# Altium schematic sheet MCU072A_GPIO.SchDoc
size 431 x 279 mm; Date: Not shown in title block; ApprovedBy: Not shown in title block; CheckedBy: Not shown in title block; Author: Not shown in title block; CompanyName: Not shown in title block; DrawnBy: Cody Watkins; Engineer: Not shown in title block; Organization: Not shown in title block; Address1: Not shown in title block; Address2: Not shown in title block; Address3: Not shown in title block; Address4: Not shown in title block; DocumentNumber: 2; Revision: Use project parameter SCH_Rev; SheetNumber: 2; SheetTotal: 7; PageSetup: Record=PageOptions¦CenterHorizontal=True¦CenterVertical=True¦PrintScale=1.00¦XCorrection=1.00¦YCorrection=1.00¦PrintKind=0¦BorderSize=5000000¦LeftOffset=0¦BottomOffset=0¦Orientation=2¦PaperLength=1000¦PaperWidth=1000¦Scale=100¦PaperSource=15¦PrintQuality=600¦MediaType=1¦DitherType=10¦PaperKind=Letter¦PrintScaleMode=1
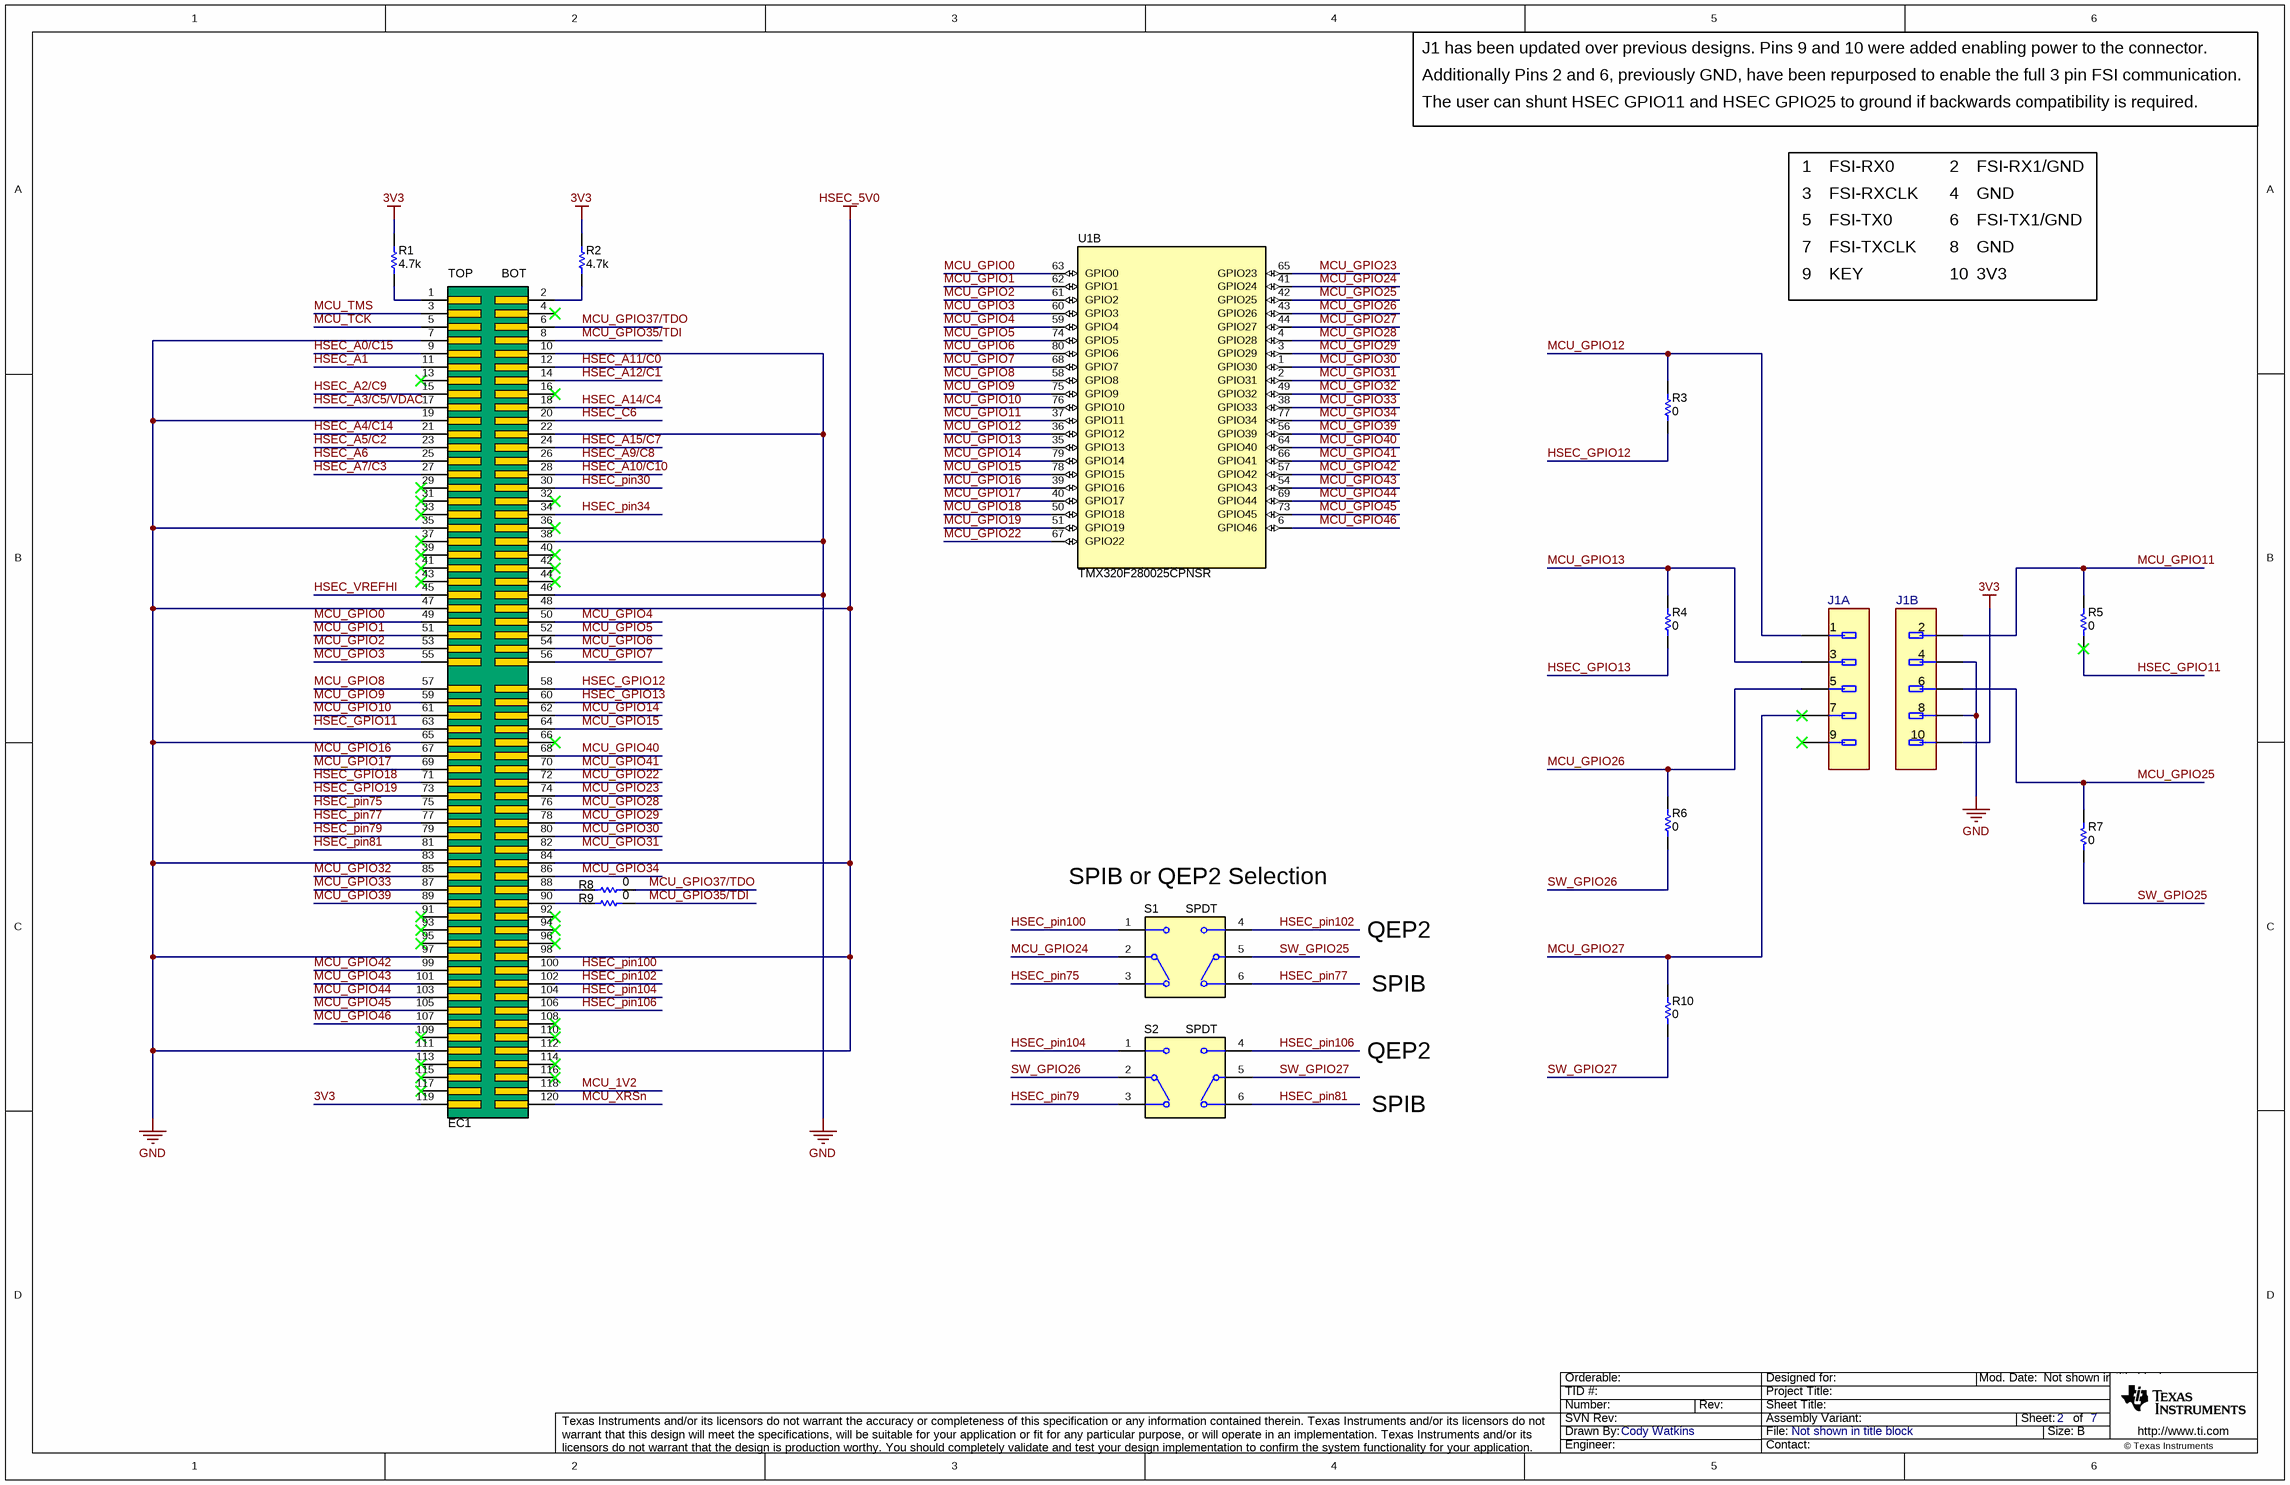
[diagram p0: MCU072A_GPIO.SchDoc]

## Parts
EC1  controlCARD-120HSEC_Edge  [controlCARD-120HSEC_Edge]  (value not drawn)  (no BOM)
J1  TMM-105-01-T-D  [FP-TMM-105-01-T-D_HDR10-MFG]  (value not drawn)  (parts A,B of 2)
R1  ValueDisplayed: 4.7k  [0402]  (hidden comment: CRCW04024K70JNED)
R2  ValueDisplayed: 4.7k  [0402]  (hidden comment: CRCW04024K70JNED)
R3  ValueDisplayed: 0  [0603]  (hidden comment: CRCW06030000Z0EA)
R4  ValueDisplayed: 0  [0603]  (hidden comment: CRCW06030000Z0EA)
R5  ValueDisplayed: 0  [0603]  (hidden comment: CRCW06030000Z0EA)
R6  ValueDisplayed: 0  [0603]  (hidden comment: CRCW06030000Z0EA)
R7  ValueDisplayed: 0  [0603]  (hidden comment: CRCW06030000Z0EA)
R8  ValueDisplayed: 0  [0603]  (hidden comment: CRCW06030000Z0EA)
R9  ValueDisplayed: 0  [0603]  (hidden comment: CRCW06030000Z0EA)
R10  ValueDisplayed: 0  [0603]  (hidden comment: CRCW06030000Z0EA)
S1  Circuit: SPDT  [SW_CAS-D20TA]  (hidden comment: CAS-D20TA)
S2  Circuit: SPDT  [SW_CAS-D20TA]  (hidden comment: CAS-D20TA)
U1  TMX320F280025CPNSR  [PN0080A_N]  (part B of 4)

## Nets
3V3: EC1.119 J1.10 R1.1 R2.2
GND: EC1.7 EC1.10 EC1.19 EC1.22 EC1.35 EC1.38 EC1.46 EC1.47 EC1.65 EC1.83 EC1.97 EC1.111 J1.4 J1.8
HSEC_5V0: EC1.48 EC1.84 EC1.98 EC1.112
HSEC_A0/C15: EC1.9
HSEC_A1: EC1.11
HSEC_A2/C9: EC1.15
HSEC_A3/C5/VDAC: EC1.17
HSEC_A4/C14: EC1.21
HSEC_A5/C2: EC1.23
HSEC_A6: EC1.25
HSEC_A7/C3: EC1.27
HSEC_A9/C8: EC1.26
HSEC_A10/C10: EC1.28
HSEC_A11/C0: EC1.12
HSEC_A12/C1: EC1.14
HSEC_A14/C4: EC1.18
HSEC_A15/C7: EC1.24
HSEC_C6: EC1.20
HSEC_GPIO11: EC1.63 R5.1
HSEC_GPIO12: EC1.58 R3.1
HSEC_GPIO13: EC1.60 R4.1
HSEC_GPIO18: EC1.71
HSEC_GPIO19: EC1.73
HSEC_pin30: EC1.30
HSEC_pin34: EC1.34
HSEC_pin75: EC1.75 S1.3
HSEC_pin77: EC1.77 S1.6
HSEC_pin79: EC1.79 S2.3
HSEC_pin81: EC1.81 S2.6
HSEC_pin100: EC1.100 S1.1
HSEC_pin102: EC1.102 S1.4
HSEC_pin104: EC1.104 S2.1
HSEC_pin106: EC1.106 S2.4
HSEC_VREFHI: EC1.45
MCU_1V2: EC1.118
MCU_GPIO0: EC1.49 U1.63(GPIO0)
MCU_GPIO1: EC1.51 U1.62(GPIO1)
MCU_GPIO2: EC1.53 U1.61(GPIO2)
MCU_GPIO3: EC1.55 U1.60(GPIO3)
MCU_GPIO4: EC1.50 U1.59(GPIO4)
MCU_GPIO5: EC1.52 U1.74(GPIO5)
MCU_GPIO6: EC1.54 U1.80(GPIO6)
MCU_GPIO7: EC1.56 U1.68(GPIO7)
MCU_GPIO8: EC1.57 U1.58(GPIO8)
MCU_GPIO9: EC1.59 U1.75(GPIO9)
MCU_GPIO10: EC1.61 U1.76(GPIO10)
MCU_GPIO11: J1.2 R5.2 U1.37(GPIO11)
MCU_GPIO12: J1.1 R3.2 U1.36(GPIO12)
MCU_GPIO13: J1.3 R4.2 U1.35(GPIO13)
MCU_GPIO14: EC1.62 U1.79(GPIO14)
MCU_GPIO15: EC1.64 U1.78(GPIO15)
MCU_GPIO16: EC1.67 U1.39(GPIO16)
MCU_GPIO17: EC1.69 U1.40(GPIO17)
MCU_GPIO18: U1.50(GPIO18)
MCU_GPIO19: U1.51(GPIO19)
MCU_GPIO22: EC1.72 U1.67(GPIO22)
MCU_GPIO23: EC1.74 U1.65(GPIO23)
MCU_GPIO24: S1.2(C) U1.41(GPIO24)
MCU_GPIO25: J1.6 R7.2 U1.42(GPIO25)
MCU_GPIO26: J1.5 R6.2 U1.43(GPIO26)
MCU_GPIO27: J1.7 R10.2 U1.44(GPIO27)
MCU_GPIO28: EC1.76 U1.4(GPIO28)
MCU_GPIO29: EC1.78 U1.3(GPIO29)
MCU_GPIO30: EC1.80 U1.1(GPIO30)
MCU_GPIO31: EC1.82 U1.2(GPIO31)
MCU_GPIO32: EC1.85 U1.49(GPIO32)
MCU_GPIO33: EC1.87 U1.38(GPIO33)
MCU_GPIO34: EC1.86 U1.77(GPIO34)
MCU_GPIO35/TDI: EC1.8 R9.1
MCU_GPIO37/TDO: EC1.6 R8.1
MCU_GPIO39: EC1.89 U1.56(GPIO39)
MCU_GPIO40: EC1.68 U1.64(GPIO40)
MCU_GPIO41: EC1.70 U1.66(GPIO41)
MCU_GPIO42: EC1.99 U1.57(GPIO42)
MCU_GPIO43: EC1.101 U1.54(GPIO43)
MCU_GPIO44: EC1.103 U1.69(GPIO44)
MCU_GPIO45: EC1.105 U1.73(GPIO45)
MCU_GPIO46: EC1.107 U1.6(GPIO46)
MCU_TCK: EC1.5
MCU_TMS: EC1.3
MCU_XRSn: EC1.120
SW_GPIO25: R7.1 S1.5(C)
SW_GPIO26: R6.1 S2.2(C)
SW_GPIO27: R10.1 S2.5(C)
NetEC1_1: EC1.1 R1.2
NetEC1_2: EC1.2 R2.1
NetEC1_88: EC1.88 R8.2
NetEC1_90: EC1.90 R9.2

Not connected (* = marked no-connect by the designer): EC1 4* 13* 16* 29* 31* 32* 33* 36* 37* 39* 40* 41* 42* 43* 44* 66* 91* 92* 93* 94* 95* 96* 108* 109* 110* 113* 114* 115* 116* 117*; J1 9*

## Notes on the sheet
- J1 has been updated over previous designs. Pins 9 and 10 were added enabling power to the connector.
- Additionally Pins 2 and 6, previously GND, have been repurposed to enable the full 3 pin FSI communication.
- The user can shunt HSEC GPIO11 and HSEC GPIO25 to ground if backwards compatibility is required.
- 1
- FSI-RX0
- 2
- FSI-RX1/GND
- 3
- 5
- FSI-RXCLK
- FSI-TX0
- 4
- 6
- FSI-TX1/GND
- GND
- 7
- 9
- FSI-TXCLK
- KEY
- 8
- 10
- 3V3
- (near S1) SPIB or QEP2 Selection
- QEP2
- SPIB

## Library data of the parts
EC1 = CMP-0003813-2: C2000 controlCARD-120HSEC Edge Connector for Samtec HSEC8-160-01-L-DV-A-BL; Manufacturer: Any; Note: The pin numbering does not match Samtec datasheet
J1 = CMP-0086568-1: Board-To-Board Connector, TMM Series, 10 Contacts, Header, 2 mm, Through Hole, 2 Rows; Manufacturer: Samtec; ContactFinish: Tin,Nickel; Voltage_V: 281V; Symbol Name: SYM-TMM-105-01-T-D; Row_Count: 2; Current_A: 3.2A
R1 R2 = CMP-0026938-5: RES, 4.7 k, 5%, 0.063 W, AEC-Q200 Grade 0, 0402; Manufacturer: Vishay-Dale; Value: 4.7k; Value_Code: 4k70; Power_W: 63mW; Value2: 0.063W; VDC_V: 50V; TempCo: 200 ppm/C; EIA_Code: E24; AEC Category: Q200; AEC Qualified: Y; AEC Grade: 0; SizeArea_mm2: 0.5; SizeX_mm: 1; SizeZ_mm: 0.6
R3-R10 = CMP-0025697-4: RES, 0, 5%, 0.1 W, AEC-Q200 Grade 0, 0603; Manufacturer: Vishay-Dale; Value: 0; Value_Code: 0000; Power_W: 100mW; Value2: 0.1W; VDC_V: 75V; TempCo: 200 ppm/C; EIA_Code: E24; AEC Category: Q200; AEC Qualified: Y; SizeArea_mm2: 1.28; SizeX_mm: 1.6; SizeY_mm: 0.8; SizeZ_mm: 1
S1 S2 = CMP-0002233-1: Switch, Dual SPDT,  2 Pos, 0.1A, 6VDC, SMD; Manufacturer: Copal Electronics; VDC_V: 6V; SwitchFunction: On-On; PositionCount: 2; CurrentRating_mA: 100A
U1 = CMP-0750188-2: TMX320F280025CPNSR, PN0080A (LQFP-80); Alternate Manufacturer: Texas Instruments; SizeY_mm: 14; CompType: IC; AEC Category: Q200; AEC Qualified: N; SizeAreaWB_mm2: 256; SizeArea_mm2: 196; SizeZ_mm: 1.6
